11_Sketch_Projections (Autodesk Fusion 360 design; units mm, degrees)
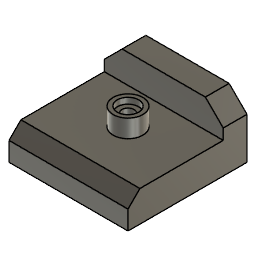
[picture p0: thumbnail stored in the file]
part number: 2026-07-16-12-20-52-273
sketch "Sketch1" plane through (0, 0, 0) normal (1, 0, 0) x axis (0, 1, 0)
  line L1 (-50, 0) -> (0, 0)
  line L2 (-50, 16) -> (-50, 0)
  line L3 (-40, 26) -> (-50, 16)
  line L4 (30, 26) -> (-40, 26)
  line L5 (30, 50) -> (30, 26)
  line L6 (50, 50) -> (30, 50)
  line L7 (50, 0) -> (50, 50)
  line L8 (0, 0) -> (50, 0)
  point P1 (0, 0)
  point P2 (0, 0)
  point P3 (-50, 0)
  point P4 (-50, 16)
  point P5 (-40, 26)
  point P7 (30, 50)
  point P8 (50, 50)
  point P9 (50, 0)
  coincident P1 P2
  horizontal L1
  perpendicular L1 L2
  perpendicular L2 L4
  perpendicular L4 L5
  perpendicular L5 L6
  perpendicular L1 L7
  perpendicular L7 L8
  equal L1 L8
  dimension "d1" distance P2 P3 = 50
  dimension "d2" distance P3 P4 = 16
  dimension "d3" angle L2 L3 = 45
  dimension "d4" distance P4 P5 = 10
  dimension "d5" distance P7 P8 = 20
  dimension "d6" distance P8 P9 = 50
extrude "Extrude1" new body sketch "Sketch1" distance 100
sketch "Sketch2" plane through (0, 0, 26) normal (0, 0, 1) x axis (-1, 0, 0)
  line L1 (-50, 40) -> (50, 40)
  line L2 (-50, -30) -> (-50, 40)
  line L3 (50, -30) -> (-50, -30)
  line L4 (50, 40) -> (50, -30)
  circle C1 centre (0, 0) radius 12.5
  point P1 (0, 0)
  point P6 (0, 0)
  coincident P1 P6
  dimension "d9" diameter C1 = 25
extrude "Extrude2" add sketch "Sketch2" profile of C1 along normal blind 15
chamfer "Chamfer1" distance 15
hole "Hole1" HoleDiameter 10 TipAngle 118 CBDepth 5 CBDiameter 18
